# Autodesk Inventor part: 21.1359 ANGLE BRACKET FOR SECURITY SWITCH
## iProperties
Created: 2007-05
Part Number: 21.1359 ANGLE BRACKET FOR SECURITY SWITCH
Document SubType Name: Modeling
Designer: Andy Moles
Material: Aluminum-6061
Mass: 98.0756 g
Surface Area: 179.157 cm^2
Volume: 36.1903 cm^3
Density: 2.71 g/cm^3
Author: Andy Moles
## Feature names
1. Extrusion1
2. Extrusion2
3. Hole1
